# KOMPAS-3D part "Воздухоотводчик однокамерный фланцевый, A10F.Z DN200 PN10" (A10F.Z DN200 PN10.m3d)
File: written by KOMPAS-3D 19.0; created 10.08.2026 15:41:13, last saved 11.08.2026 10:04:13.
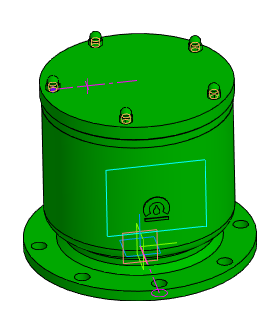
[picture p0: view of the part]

Document properties: Автор: Энергия; Полное имя файла: Z:\3.Личные\kachalov\001_3d для проектировщиков\x.x Тип A10F.Z Воздухоотводчик однокамерный фланцевый\A10F.Z DN200 PN10.m3d

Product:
- Part/product: Воздухоотводчик однокамерный фланцевый  | designation A10F.Z DN200 PN10
    Масса: 65.222
  - Component [standard]: Гайка М12-6H (S18) ГОСТ 11860-85  | qty 5  | Масса: 0.02606; Раздел спецификации: Стандартные изделия; Рассекать на разрезах: no; source file: C:\Program Files\ASCON\KOMPAS-3D v19\Libs\PARTLib\DATA\vault\Methods\Kompas\3D\PLib_Blind_Nut_type1_900.m3d
  - Body: Тело 1
      Масса: 65.1699

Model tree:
1. Эскиз:1
2. Элемент вращения:1
     Угол 1 = 360
3. Скругление:1  (with: Элемент вращения:1)
     Радиус = 10
4. Фаска:1  (with: Элемент вращения:1)
     Угол = 45; Длина 1 = 10; Длина 2 = 10
5. Эскиз:2  (with: Элемент вращения:1)
6. Точка:1
     Y = -122.5; Z = 273; Координата Y = -122.5; Координата Z = 273
7. Массив по концентрической сетке:1  (with: Элемент вращения:1)  (5 pattern instances)
     Шаг 2 = 360
8. Эскиз:3  (with: Элемент вращения:1)
9. Элемент выдавливания:1  (with: Элемент вращения:1, Массив по концентрической сетке:1, Эскиз:3)  (8 pattern instances)
     Расстояние 2 = 16; N 1 = 1; Шаг 1 = 10; Шаг 2 = 360; Номер 1 = 1
10. Касательная плоскость:1  (with: Элемент вращения:1)
11. Эскиз:4
12. Элемент выдавливания:2  (with: Элемент вращения:1)  (labels: Фаска наружная:1)
     Расстояние 1 = 1; Ориентация = 2

Expressions: Dn/2; D2/2; D/2; B/2; H/2; D1/2-10; D1-50
Referenced files in C:\Program Files\ASCON\KOMPAS-3D v19\Libs\PARTLib\DATA\vault\Methods\Kompas\3D\: PLib_Blind_Nut_type1_900.m3d
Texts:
  A10F.Z DN200 PN10
  Гайка М12-6H (S18) ГОСТ 11860-85 (1)
  foc1
  foc2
